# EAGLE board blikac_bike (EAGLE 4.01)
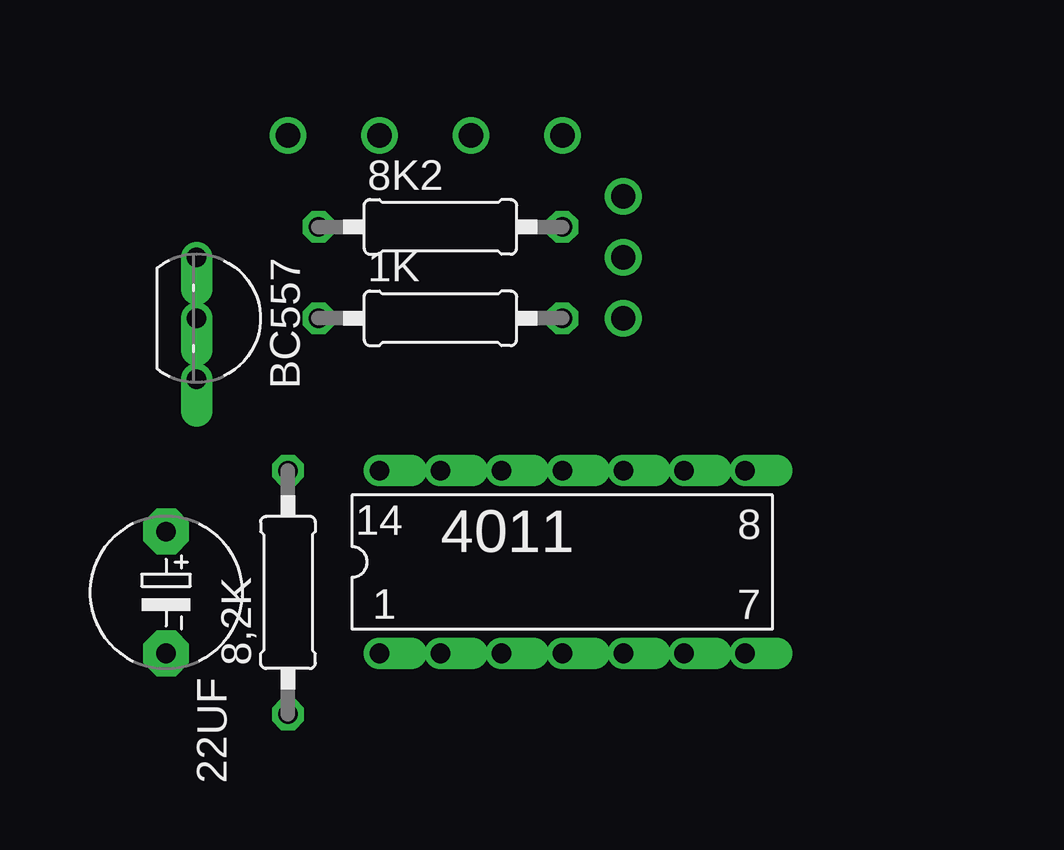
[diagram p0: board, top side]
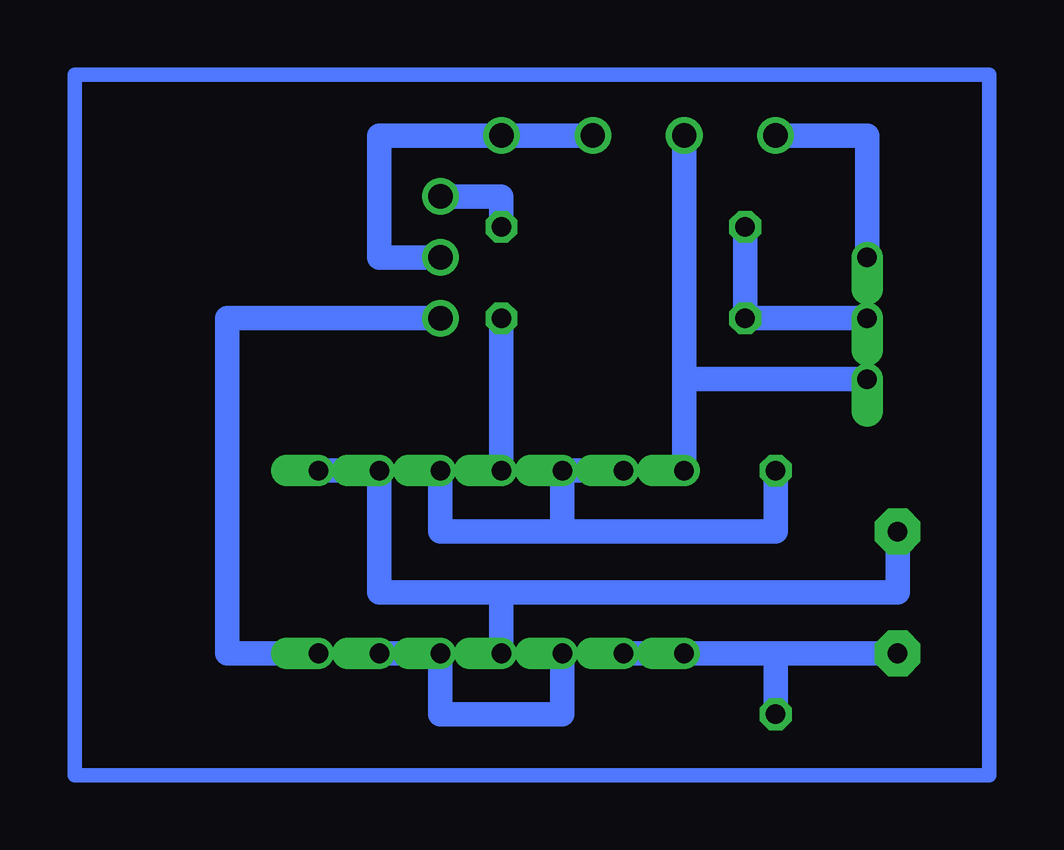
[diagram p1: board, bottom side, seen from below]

No outline drawn. Coordinates in mm, seen from the top.
Copper layers used: Bottom

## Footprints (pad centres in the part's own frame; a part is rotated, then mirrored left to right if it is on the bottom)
0207/10 = drill 0.813 octagon: 1 -5.08,0; 2 5.08,0
E5-6 = drill 0.813 pad 1.905 octagon: + -2.54,0; - 2.54,0
DIL14 = drill 0.813 offset: 1 -7.62,-3.81; 2 -5.08,-3.81; 3 -2.54,-3.81; 4 0,-3.81; 5 2.54,-3.81; 6 5.08,-3.81; 7 7.62,-3.81; 8 7.62,3.81; 9 5.08,3.81; 10 2.54,3.81; 11 0,3.81; 12 -2.54,3.81; 13 -5.08,3.81; 14 -7.62,3.81
TO92- = drill 0.813 offset: 1 2.54,-1.27; 2 0,-1.27; 3 -2.54,-1.27

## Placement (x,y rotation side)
1K  [0207/10]  40.64,60.96 0 top
8,2K  [0207/10]  34.29,49.53 90 top
8K2  [0207/10]  40.64,64.77 0 top
22UF  [E5-6]  29.21,49.53 270 top
4011  [DIL14]  45.72,50.8 0 top
BC557  [TO92-]  31.75,60.96 270 top

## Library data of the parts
1K 8,2K 8K2 22UF = rcl
4011 = 40xx
BC557 = transistor-pnp

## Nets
S$1: 8,2K.1 22UF.- 4011.1 4011.2
S$2: 4011.3 4011.5 4011.6
S$3: 22UF.+ 4011.4 4011.8 4011.9
S$4: 8,2K.2 4011.10 4011.12 4011.13
S$5: 1K.1 8K2.1 BC557.2
S$6: 1K.2 4011.11
S$7: BC557.3
S$10: 4011.7
S$12: 8K2.2
S$13: 4011.14 BC557.1

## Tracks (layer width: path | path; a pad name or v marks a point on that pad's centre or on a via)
S$1
  Bottom 1.016: 4011.2 4011.1 34.29,46.99 | 8,2K.1 34.29,46.99 | 22UF.- 34.29,46.99
S$2
  Bottom 1.016: 4011.3 43.18,44.45 48.26,44.45 4011.5 4011.6
S$3
  Bottom 1.016: 4011.8 4011.9 50.8,49.53 45.72,49.53 | 4011.4 45.72,49.53 | 45.72,49.53 29.21,49.53 22UF.+
S$4
  Bottom 1.016: 4011.10 48.26,52.07 43.18,52.07 | 43.18,52.07 4011.12 4011.13 | 43.18,52.07 34.29,52.07 8,2K.2
S$5
  Bottom 1.016: BC557.2 1K.1 8K2.1
S$6
  Bottom 1.016: 4011.11 1K.2
S$7  (via drill 1.02)
  Bottom 1.016: BC557.3 30.48,68.58 v34.29,68.58
S$9
  Bottom 0.61: 25.4,41.91 63.5,41.91 63.5,71.12 25.4,71.12 25.4,41.91
S$10  (via drill 1.02)
  Bottom 1.016: v48.26,60.96 57.15,60.96 57.15,46.99 4011.7
S$11  (via drill 1.02)
  Bottom 1.016: v41.91,68.58 v45.72,68.58 50.8,68.58 50.8,63.5 v48.26,63.5
S$12  (via drill 1.02)
  Bottom 1.016: v48.26,66.04 45.72,66.04 8K2.2
S$13  (via drill 1.02)
  Bottom 1.016: BC557.1 38.1,58.42 | 38.1,58.42 4011.14 | 38.1,58.42 v38.1,68.58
